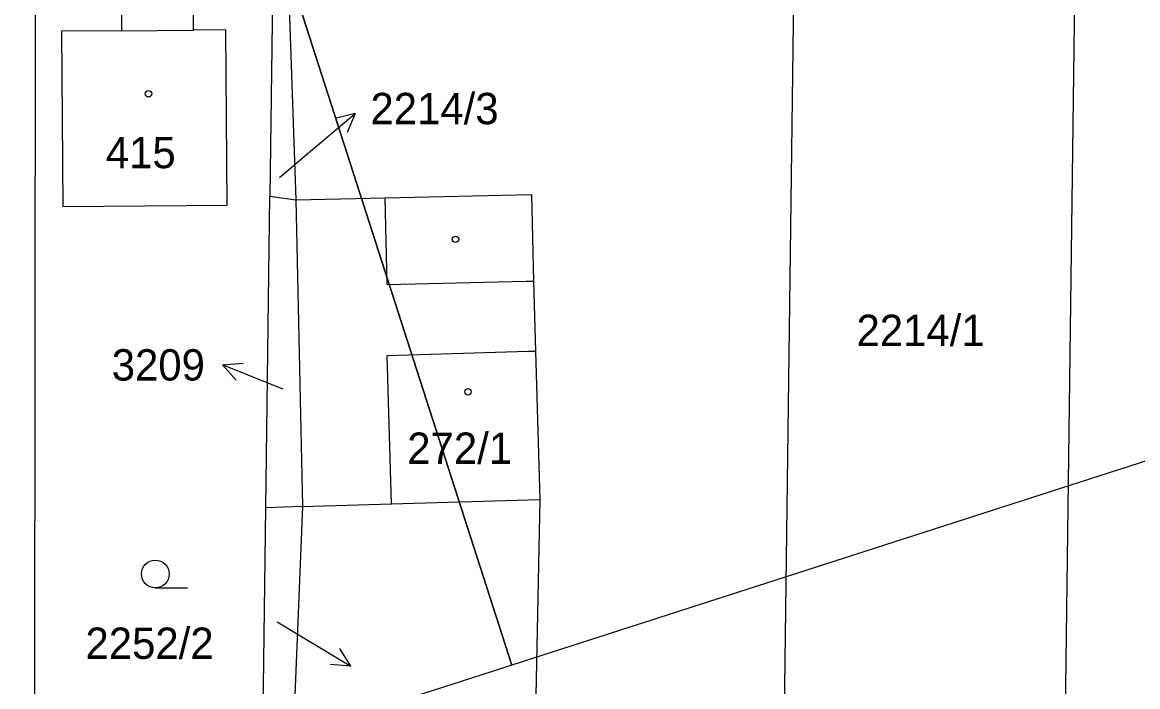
# Model space of a CAD drawing. Extents: x -758836 to -757729, y -1175316 to -1174366.
# Drawn here: x -758198.7 to -758138.2, y -1174833.4 to -1174797.3 of the extents above; entities that cross this region are included whole.
import ezdxf

# ---------------------------------------------------------------- set-up
doc = ezdxf.new("R2010")
doc.units = 0
for name, color, linetype in [('_NOR-pomocná', 7, 'Continuous'), ('Hranice parcel', 7, 'Continuous'), ('Parcelní čísla', 7, 'Continuous'), ('Pop  PČ popisy', 7, 'Continuous'), ('Vnitřní kresba', 7, 'Continuous'), ('Značky budov', 7, 'Continuous'), ('Značky kultur', 7, 'Continuous')]:
    doc.layers.add(name, color=color, linetype=linetype)

msp = doc.modelspace()

# ---------------------------------------------------------------- linework, layer by layer
at = {"layer": '_NOR-pomocná'}
for points in [[(-758217.708, -1174690.839), (-758117.765, -1174658.647), (-758072.236, -1174799.995), (-758172.179, -1174832.187)], [(-758317.652, -1174723.031), (-758217.708, -1174690.839), (-758172.179, -1174832.187), (-758272.123, -1174864.38)]]:
    msp.add_lwpolyline(points, close=True, dxfattribs=at)
at = {"layer": 'Hranice parcel'}
for p, q in [((-758156.63, -1174775.13), (-758157.87, -1174870.96)), ((-758143.14, -1174911.79), (-758141.37, -1174774.78)), ((-758184.92, -1174776.46), (-758185.31, -1174806.74)), ((-758184.92, -1174776.46), (-758183.9, -1174806.95)), ((-758185.53, -1174823.65), (-758185.31, -1174806.74)), ((-758185.31, -1174806.74), (-758183.9, -1174806.95)), ((-758183.9, -1174806.95), (-758183.53, -1174823.59)), ((-758186.22, -1174876.87), (-758185.53, -1174823.65)), ((-758183.53, -1174823.59), (-758185.73, -1174876.96)), ((-758183.53, -1174823.59), (-758185.53, -1174823.65)), ((-758170.66, -1174823.2), (-758171.67, -1174870.63))]:
    msp.add_line(p, q, dxfattribs=at)
for points in [[(-758198.02, -1174777.55), (-758198.11, -1174871.18), (-758198.12, -1174878.49)], [(-758196.6, -1174797.79), (-758196.54, -1174807.31), (-758187.63, -1174807.24), (-758187.69, -1174797.73), (-758189.45, -1174797.74), (-758189.47, -1174795.54), (-758193.37, -1174795.47), (-758193.36, -1174797.77), (-758196.6, -1174797.79)], [(-758183.9, -1174806.95), (-758179.06, -1174806.83), (-758171.11, -1174806.65), (-758171, -1174811.35), (-758170.9, -1174815.15), (-758170.66, -1174823.2)], [(-758183.53, -1174823.59), (-758178.71, -1174823.44), (-758170.66, -1174823.2)]]:
    msp.add_lwpolyline(points, dxfattribs=at)
at = {"layer": 'Pop  PČ popisy'}
for p, q in [((-758182.97, -1174804.2), (-758180.671, -1174802.271)), ((-758180.671, -1174802.271), (-758181.76, -1174802.531)), ((-758180.671, -1174802.271), (-758181.116, -1174803.298)), ((-758184.79, -1174805.73), (-758182.97, -1174804.2)), ((-758187.872, -1174815.896), (-758186.756, -1174815.807)), ((-758185.09, -1174817.02), (-758187.872, -1174815.896)), ((-758187.872, -1174815.896), (-758187.132, -1174816.735)), ((-758184.59, -1174817.22), (-758185.09, -1174817.02)), ((-758184.9, -1174829.84), (-758183.49, -1174830.69)), ((-758183.49, -1174830.69), (-758180.918, -1174832.236)), ((-758180.918, -1174832.236), (-758181.518, -1174831.291)), ((-758180.918, -1174832.236), (-758182.034, -1174832.149))]:
    msp.add_line(p, q, dxfattribs=at)
at = {"layer": 'Vnitřní kresba'}
for p, q in [((-758193.36, -1174797.77), (-758189.45, -1174797.74)), ((-758178.95, -1174811.53), (-758179.06, -1174806.83)), ((-758178.95, -1174811.53), (-758171.4, -1174811.36)), ((-758171.4, -1174811.36), (-758171, -1174811.35)), ((-758178.95, -1174815.39), (-758171.3, -1174815.16)), ((-758171.3, -1174815.16), (-758170.9, -1174815.15)), ((-758178.71, -1174823.44), (-758178.95, -1174815.39))]:
    msp.add_line(p, q, dxfattribs=at)
at = {"layer": 'Značky budov'}
for centre in [(-758191.887, -1174801.189), (-758175.237, -1174809.089), (-758174.557, -1174817.359)]:
    msp.add_circle(centre, 0.175, dxfattribs=at)
at = {"layer": 'Značky kultur'}
msp.add_line((-758191.521, -1174827.992), (-758189.771, -1174827.992), dxfattribs=at)
msp.add_circle((-758191.52, -1174827.242), 0.75, dxfattribs=at)

# ---------------------------------------------------------------- texts
at = {"layer": 'Parcelní čísla'}
for s, p in [('2214/3', (-758179.85, -1174802.843)), ('415', (-758194.204, -1174805.23)), ('2214/1', (-758153.486, -1174814.875)), ('3209', (-758193.884, -1174816.75)), ('272/1', (-758177.853, -1174821.27)), ('2252/2', (-758195.308, -1174831.85))]:
    msp.add_text(s, height=1.7, dxfattribs=at).set_placement(p)

doc.saveas('drawing.dxf')
